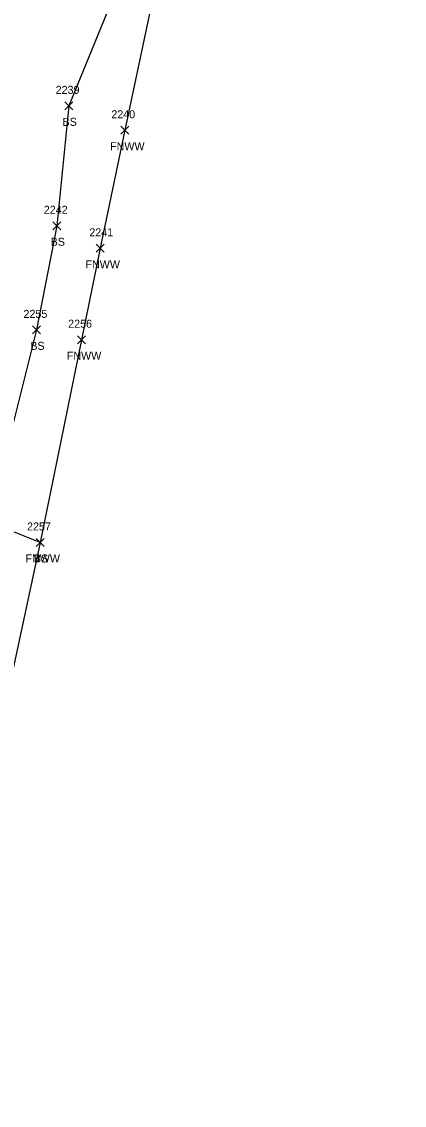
# Model space of a CAD drawing. Extents: x 1483143 to 1488182, y 802902 to 807581.
# Drawn here: x 1488010.4 to 1488106, y 806404.6 to 806675.5 of the extents above; entities that cross this region are included whole.
import ezdxf

# ---------------------------------------------------------------- set-up
doc = ezdxf.new("R2010")
doc.units = 0
for name, color, linetype in [('L_A', 7, 'Continuous'), ('L_I', 7, 'Continuous'), ('L_TIC', 7, 'Continuous'), ('LELB', 7, 'Continuous'), ('LFNC', 7, 'Continuous')]:
    doc.layers.add(name, color=color, linetype=linetype)

msp = doc.modelspace()

# ---------------------------------------------------------------- linework, layer by layer
at = {"layer": 'L_TIC'}
for points in [[(1488021.17, 806653.43), (1488023.17, 806655.43)], [(1488023.17, 806653.43), (1488021.17, 806655.43)], [(1488035.14, 806647.33), (1488037.14, 806649.33)], [(1488037.14, 806647.33), (1488035.14, 806649.33)], [(1488018.2, 806623.46), (1488020.2, 806625.46)], [(1488020.2, 806623.46), (1488018.2, 806625.46)], [(1488028.99, 806617.82), (1488030.99, 806619.82)], [(1488030.99, 806617.82), (1488028.99, 806619.82)], [(1488013.13, 806597.44), (1488015.13, 806599.44)], [(1488015.13, 806597.44), (1488013.13, 806599.44)], [(1488024.33, 806594.98), (1488026.33, 806596.98)], [(1488026.33, 806594.98), (1488024.33, 806596.98)], [(1488014.01, 806544.3), (1488016.01, 806546.3)], [(1488016.01, 806544.3), (1488014.01, 806546.3)], [(1488014.01, 806544.3), (1488016.01, 806546.3)], [(1488016.01, 806544.3), (1488014.01, 806546.3)]]:
    msp.add_lwpolyline(points, dxfattribs=at)
at = {"layer": 'LELB'}
for points in [[(1488057.62, 806804.31), (1488053.28, 806778.75), (1488055.57, 806759.29), (1488045.22, 806727.88), (1488037.59, 806692.17), (1488022.17, 806654.43), (1488019.2, 806624.46), (1488014.13, 806598.44), (1488002.07, 806550.47)], [(1488015.01, 806545.3), (1488002.07, 806550.47), (1487985.68, 806558.93), (1487980.48, 806572.93)]]:
    msp.add_lwpolyline(points, dxfattribs=at)
at = {"layer": 'LFNC'}
msp.add_lwpolyline([(1488105.96, 806931.77), (1488093.97, 806892.24), (1488086.74, 806870.75), (1488078.76, 806844.27), (1488074.64, 806830.72), (1488062.83, 806775.27), (1488057.88, 806751.49), (1488052.32, 806724.88), (1488045.16, 806690.9), (1488036.14, 806648.33), (1488029.99, 806618.82), (1488025.33, 806595.98), (1488015.01, 806545.3), (1488004.88, 806498.25), (1488001.38, 806481.96), (1487997.71, 806465.14), (1487995.36, 806451.92), (1487987.25, 806418.51), (1487973.91, 806378.22)], dxfattribs=at)

# ---------------------------------------------------------------- texts
at = {"layer": 'L_A'}
for s, p in [('BS', (1488020.61, 806649.43)), ('FNWW', (1488032.49, 806643.33)), ('BS', (1488017.64, 806619.46)), ('FNWW', (1488026.34, 806613.82)), ('BS', (1488012.57, 806593.44)), ('FNWW', (1488021.68, 806590.98)), ('FNWW', (1488011.35, 806540.3)), ('BS', (1488013.45, 806540.3))]:
    msp.add_text(s, height=2, dxfattribs=at).set_placement(p)
at = {"layer": 'L_I'}
for s, p in [('2239', (1488018.9, 806657.43)), ('2240', (1488032.8, 806651.33)), ('2242', (1488015.94, 806627.46)), ('2241', (1488027.3, 806621.82)), ('2255', (1488010.87, 806601.44)), ('2256', (1488022.02, 806598.98)), ('2257', (1488011.75, 806548.3)), ('2257', (1488011.75, 806548.3))]:
    msp.add_text(s, height=2, dxfattribs=at).set_placement(p)

doc.saveas('drawing.dxf')
